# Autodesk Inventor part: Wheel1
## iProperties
Created: 2010-08
Part Number: Wheel1
Document SubType Name: Modeling
Designer: nguyenducthang
Density: 1 g/cm^3
Mass: 8.46922 g
Surface Area: 87.1237 cm^2
Volume: 8.46922 cm^3
Author: nguyenducthang
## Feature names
1. Revolution2
2. Extrusion16
3. Circular Pattern3
4. Extrusion17
5. Circular Pattern4
